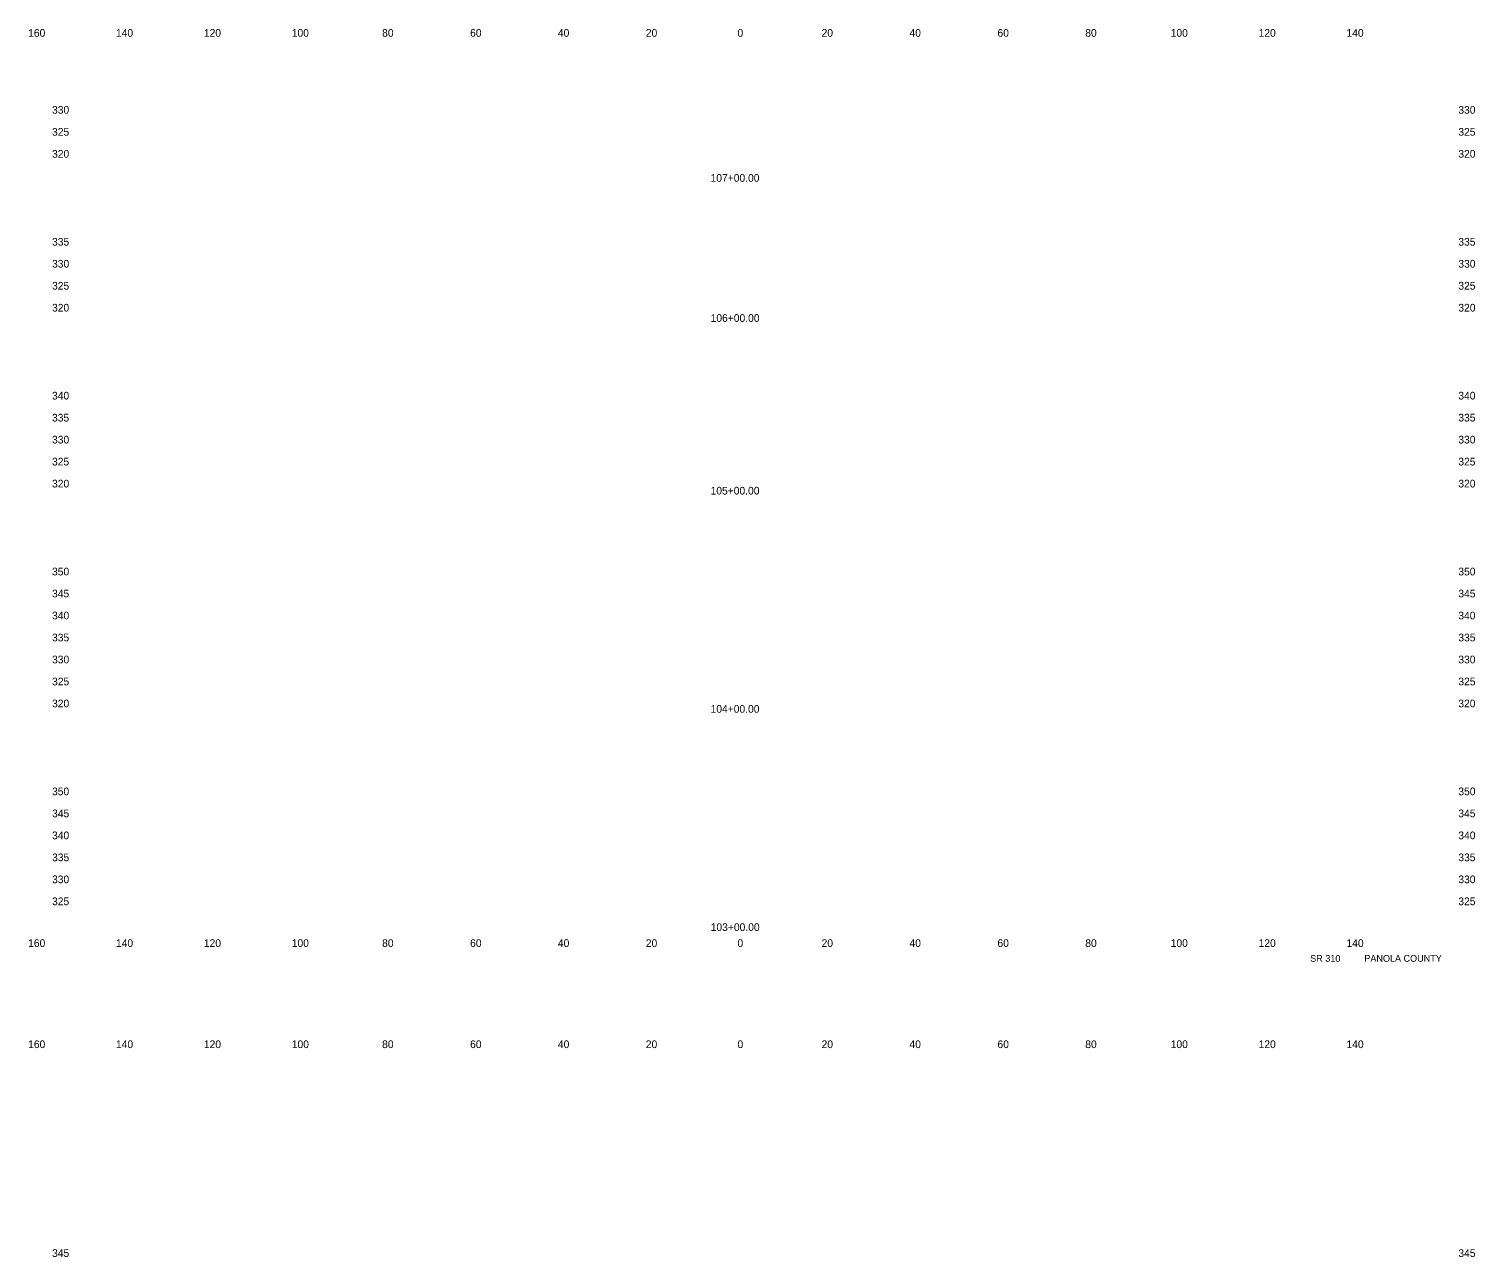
# Model space of a CAD drawing. Extents: x 21481 to 21810, y 6485 to 11067.
# Drawn here: x 21480.9 to 21809.9, y 7337.7 to 7617 of the extents above; entities that cross this region are included whole.
import ezdxf

# ---------------------------------------------------------------- set-up
doc = ezdxf.new("R2010")
doc.units = 0
for name, color, linetype in [('62', 7, 'Continuous'), ('XS_CELL', 7, 'Continuous'), ('XS_P_TX_DCH', 7, 'Continuous'), ('XS_P_TX_FS_BS', 7, 'Continuous')]:
    doc.layers.add(name, color=color, linetype=linetype)

msp = doc.modelspace()

# ---------------------------------------------------------------- texts
at = {"layer": '62'}
for s, p in [('  160  ', (21479.4, 7615.21)), ('  140  ', (21499.39, 7615.21)), ('  120  ', (21519.39, 7615.21)), ('  100  ', (21539.39, 7615.21)), ('  80  ', (21559.95, 7615.21)), ('  60  ', (21579.97, 7615.21)), ('  40  ', (21599.95, 7615.21)), ('  20  ', (21619.95, 7615.21)), ('  0  ', (21640.81, 7615.21)), ('  0  ', (21640.81, 7615.21)), ('  20  ', (21659.95, 7615.21)), ('  40  ', (21679.95, 7615.21)), ('  60  ', (21699.97, 7615.21)), ('  80  ', (21719.95, 7615.21)), ('  100  ', (21739.39, 7615.21)), ('  120  ', (21759.39, 7615.21)), ('  140  ', (21779.39, 7615.21)), ('  160  ', (21479.4, 7408.21)), ('  140  ', (21499.39, 7408.21)), ('  120  ', (21519.39, 7408.21)), ('  100  ', (21539.39, 7408.21)), ('  80  ', (21559.95, 7408.21)), ('  60  ', (21579.97, 7408.21)), ('  40  ', (21599.95, 7408.21)), ('  20  ', (21619.95, 7408.21)), ('  0  ', (21640.81, 7408.21)), ('  0  ', (21640.81, 7408.21)), ('  20  ', (21659.95, 7408.21)), ('  40  ', (21679.95, 7408.21)), ('  60  ', (21699.97, 7408.21)), ('  80  ', (21719.95, 7408.21)), ('  100  ', (21739.39, 7408.21)), ('  120  ', (21759.39, 7408.21)), ('  140  ', (21779.39, 7408.21)), ('  160  ', (21479.4, 7385.21)), ('  140  ', (21499.39, 7385.21)), ('  120  ', (21519.39, 7385.21)), ('  100  ', (21539.39, 7385.21)), ('  80  ', (21559.95, 7385.21)), ('  60  ', (21579.97, 7385.21)), ('  40  ', (21599.95, 7385.21)), ('  20  ', (21619.95, 7385.21)), ('  0  ', (21640.81, 7385.21)), ('  0  ', (21640.81, 7385.21)), ('  20  ', (21659.95, 7385.21)), ('  40  ', (21679.95, 7385.21)), ('  60  ', (21699.97, 7385.21)), ('  80  ', (21719.95, 7385.21)), ('  100  ', (21739.39, 7385.21)), ('  120  ', (21759.39, 7385.21)), ('  140  ', (21779.39, 7385.21))]:
    msp.add_text(s, height=1.75, dxfattribs=at).set_placement(p)
at = {"layer": 'XS_CELL'}
for s, p in [('  330  ', (21484.84, 7597.71)), ('  330  ', (21804.84, 7597.71)), ('  325  ', (21484.84, 7592.71)), ('  325  ', (21804.84, 7592.71)), ('  320  ', (21484.84, 7587.71)), ('  320  ', (21804.84, 7587.71)), ('  335  ', (21484.84, 7567.71)), ('  335  ', (21804.84, 7567.71)), ('  330  ', (21484.84, 7562.71)), ('  330  ', (21804.84, 7562.71)), ('  325  ', (21484.84, 7557.71)), ('  325  ', (21804.84, 7557.71)), ('  320  ', (21484.84, 7552.71)), ('  320  ', (21804.84, 7552.71)), ('  340  ', (21484.84, 7532.71)), ('  340  ', (21804.84, 7532.71)), ('  335  ', (21484.84, 7527.71)), ('  335  ', (21804.84, 7527.71)), ('  330  ', (21484.84, 7522.71)), ('  330  ', (21804.84, 7522.71)), ('  325  ', (21484.84, 7517.71)), ('  325  ', (21804.84, 7517.71)), ('  320  ', (21484.84, 7512.71)), ('  320  ', (21804.84, 7512.71)), ('  350  ', (21484.84, 7492.71)), ('  350  ', (21804.84, 7492.71)), ('  345  ', (21484.84, 7487.71)), ('  345  ', (21804.84, 7487.71)), ('  340  ', (21484.84, 7482.71)), ('  340  ', (21804.84, 7482.71)), ('  335  ', (21484.84, 7477.71)), ('  335  ', (21804.84, 7477.71)), ('  330  ', (21484.84, 7472.71)), ('  330  ', (21804.84, 7472.71)), ('  325  ', (21484.84, 7467.71)), ('  325  ', (21804.84, 7467.71)), ('  320  ', (21484.84, 7462.71)), ('  320  ', (21804.84, 7462.71)), ('  350  ', (21484.84, 7442.71)), ('  350  ', (21804.84, 7442.71)), ('  345  ', (21484.84, 7437.71)), ('  345  ', (21804.84, 7437.71)), ('  340  ', (21484.84, 7432.71)), ('  340  ', (21804.84, 7432.71)), ('  335  ', (21484.84, 7427.71)), ('  335  ', (21804.84, 7427.71)), ('  330  ', (21484.84, 7422.71)), ('  330  ', (21804.84, 7422.71)), ('  325  ', (21484.84, 7417.71)), ('  325  ', (21804.84, 7417.71)), ('  345  ', (21484.84, 7337.71)), ('  345  ', (21804.84, 7337.71))]:
    msp.add_text(s, height=1.75, dxfattribs=at).set_placement(p)
at = {"layer": 'XS_P_TX_DCH'}
for s, p in [('  107+00.00  ', (21634.69, 7582.23)), ('  106+00.00  ', (21634.7, 7550.37)), ('  105+00.00  ', (21634.69, 7511.1)), ('  104+00.00  ', (21634.69, 7461.48)), ('  103+00.00  ', (21634.72, 7411.84))]:
    msp.add_text(s, height=1.75, dxfattribs=at).set_placement(p)
at = {"layer": 'XS_P_TX_FS_BS'}
for s, p in [('SR 310', (21772.43, 7404.84)), ('SR 310', (21772.43, 7404.84)), ('SR 310', (21772.43, 7404.84)), ('PANOLA COUNTY', (21784.75, 7404.84)), ('PANOLA COUNTY', (21784.75, 7404.84)), ('PANOLA COUNTY', (21784.75, 7404.84))]:
    msp.add_text(s, height=1.54, dxfattribs=at).set_placement(p)

doc.saveas('drawing.dxf')
